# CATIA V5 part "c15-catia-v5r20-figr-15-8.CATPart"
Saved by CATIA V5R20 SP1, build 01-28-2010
Part number: Part1
Bounding box of the stored display mesh (mm): x -50 to 50, y -32.5 to 33.5, z -52 to 1
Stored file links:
  D:\v5_r20\psrt_files_downloaded\c15\c15-catia-v5r20-figr-15-8.CATPart
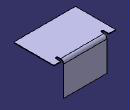
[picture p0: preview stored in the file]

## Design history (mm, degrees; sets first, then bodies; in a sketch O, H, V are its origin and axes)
SheetMetalParameters1: Thickness 1, BendRadius 4, KFactor 0.475772 {= log(min(100,max(20*SheetMetalParameters1.BendRadius,SheetMetalParameters1.Thickness)/SheetMetalParameters1.Thickness))/log(100)/2}, ReliefRadialLength 4, ReliefAxialLength 4, MinimumBendRadius 0
Body1 (main body)
  Sketch1 on xy-plane, origin (0, 0, 0), H (1, 0, 0), V (0, 1, 0)
    line L1 (-50, 32.5) -> (50, 32.5)
    line L2 (50, 32.5) -> (50, -32.5)
    line L3 (50, -32.5) -> (-50, -32.5)
    line L4 (-50, -32.5) -> (-50, 32.5)
    length L1 = 100
    length L2 = 65
    horizontal: L1 H, L3 H
    vertical: L2 V, L4 V
    symmetry: L4 L2 V, L1 L3 H
  Wall1: Thickness 1, Profile Sketch1
  d_NewWallOnEdge1: NewWallOnEdge_Edge edge [face of Wall1 | face of Wall1], NewWallOnEdge_Length 53, NewWallOnEdge_HeightLimitOffset 0, NewWallOnEdge_WidthOffset1 -15, NewWallOnEdge_WidthOffset2 -15, NewWallOnEdge_Angle 90, NewWallOnEdge_BendRadiusValue 4 {= SheetMetalParameters1.BendRadius}, NewWallOnEdge_BendTable SheetMetalParameters1, KFacteur 0.475772 {= log(min(100,max(20*d_NewWallOnEdge1.Radius,SheetMetalParameters1.Thickness)/SheetMetalParameters1.Thickness))/log(100)/2}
